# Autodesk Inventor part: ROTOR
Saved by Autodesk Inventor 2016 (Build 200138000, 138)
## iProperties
Created: 2013-10
Part Number: ROTOR
Material: solidworks materials|Cuivre
Document SubType Name: Modeling
Designer: Bruno
Density: 8.9 g/cm^3
Appearance: 214,119,94
Author: Bruno
Sending System: SolidWorks 2013
Last Author: christophe
Last Saved: 2014-02-15
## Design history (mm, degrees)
feature "Révolution2"
node "Solide1"
